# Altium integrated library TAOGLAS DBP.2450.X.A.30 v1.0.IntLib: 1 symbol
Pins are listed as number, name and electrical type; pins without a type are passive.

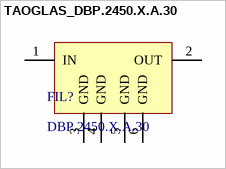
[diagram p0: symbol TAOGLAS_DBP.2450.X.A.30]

## TAOGLAS_DBP.2450.X.A.30
designator FIL?, comment DBP.2450.X.A.30
Dielectric Band Pass Filter for 2450MHz Bandwidth 100MHz; ComponentLibStatus: Created; MFG: Taoglas; Temp_High: +85C; Temp_Low: -40C
footprint TAOGLAS_DBP.2450.X.A.30 (Dielectric Band Pass Filter for 2450MHz Bandwidth 100MHz)
pins: 1 IN, 2 OUT, 3 GND, 4 GND, 5 GND, 6 GND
